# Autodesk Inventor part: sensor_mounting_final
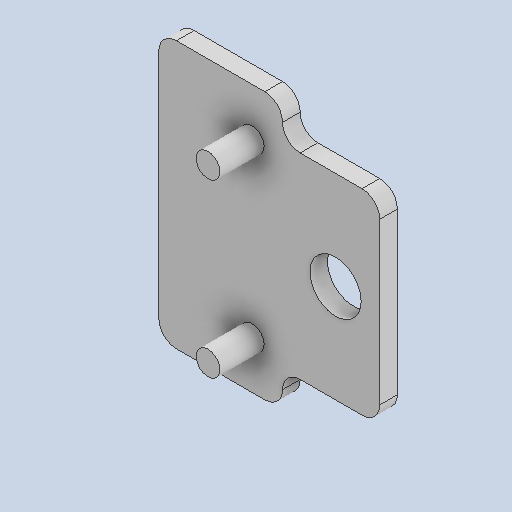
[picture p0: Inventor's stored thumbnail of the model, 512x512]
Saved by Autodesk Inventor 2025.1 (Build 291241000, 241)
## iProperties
Created: 2024-12
Part Number: sensor_mounting_final
Material: Generic
Document SubType Name: Modeling
Designer: mansa
Density: 1 g/cm^3
Appearance: Default
Author: mansa
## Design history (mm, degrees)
sketch "Sketch1"
  geometry: L1 (-25, 0)-(-25, 22.2); L2 (-11, 22.2)-(0, 22.2); L3 (0, 22.2)-(0, 0); L4 (-25, 11.1)-(0, 11.1); L5 (-5, 22.679)-(-5, -0.479); L6 (-11, 22.2)-(-11, 26.2); L7 (-11, 26.2)-(-25, 26.2); L8 (-25, 26.2)-(-25, 22.2); L9 (-11, 0)-(0, 0); L10 (-11, 0)-(-11, -4); L11 (-11, -4)-(-25, -4); L12 (-25, -4)-(-25, 0); C1 r 2.9 at (-5, 11.1)
  constraints: 24 end point, 3 midpoint, 3 symmetric about line, 2 collinear, 2 perpendicular, 1 centre point, 1 horizontal, 1 parallel, 1 point on line, 1 vertical
  dimensions: "d0" = 25 distance of L1.end L2.end; "d1" = 22.2 distance of L1.start L1.end; "d2" = 5.8 diameter of C1; "d3" = 5 distance between parallel lines of L3 L5; "d6" = 4 distance of L2.start L6.end; "d7" = 14 distance of L6.end L7.end; "d8" = 30.2 distance between parallel lines of L11 L7
extrude "Extrusion1" new body sketch "Sketch1" distance "d4" = 2; taper "d5" = 0 deg
feature "Surface1"
sketch "Sketch2"
  geometry: C1 r 1.55 at (-14.431, 20.8) reference; C2 r 1.55 at (-14.431, 1.4) reference; C3 r 1.35 at (-14.431, 20.8); C4 r 1.35 at (-14.431, 1.4); 1 further point
  constraints: 2 centre point, 2 coincident
  dimensions: "d9" = 0.2 radial gap between concentric circles of C1 C3; "d10" = 0.2 radial gap between concentric circles of C2 C4
extrude "Extrusion2" join sketch "Sketch2" distance "d11" = 5; taper "d12" = 0 deg
fillet "Fillet1" dims "d13" = 2
body "Solid1"
body "Srf1"
